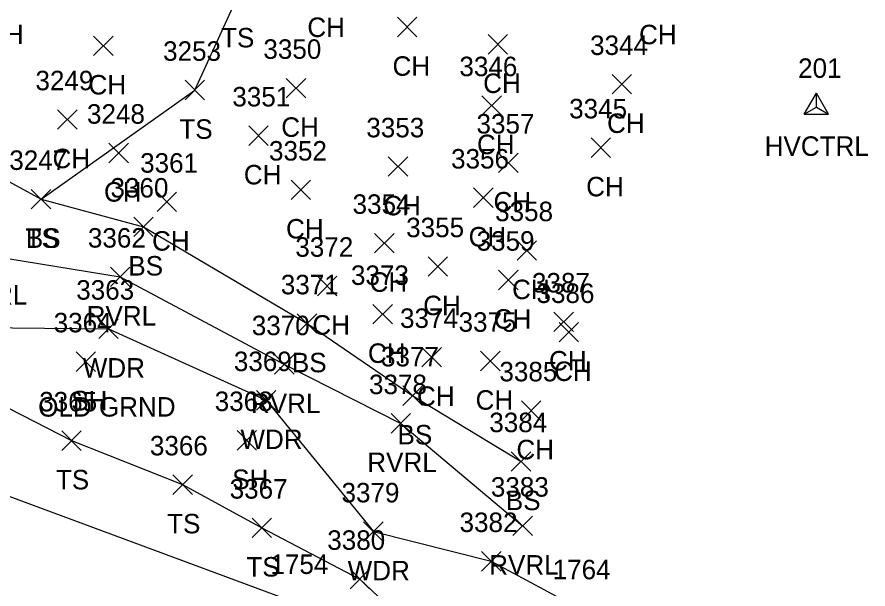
# Model space of a CAD drawing. Extents: x 462930 to 463548, y 29607 to 30453.
# Drawn here: x 463356.77 to 463383.4, y 30103.46 to 30121.35 of the extents above; entities that cross this region are included whole.
import ezdxf

# ---------------------------------------------------------------- set-up
doc = ezdxf.new("R2010")
doc.units = 0
for name, color, linetype in [('C_A', 7, 'Continuous'), ('C_I', 7, 'Continuous'), ('CPSM', 7, 'Continuous'), ('L_A', 7, 'Continuous'), ('L_C', 7, 'Continuous'), ('L_I', 7, 'Continuous'), ('L_TIC', 7, 'Continuous'), ('LAWA', 7, 'Continuous'), ('LAWE', 7, 'Continuous'), ('LELB', 7, 'Continuous')]:
    doc.layers.add(name, color=color, linetype=linetype)

msp = doc.modelspace()

# ---------------------------------------------------------------- linework, layer by layer
at = {"layer": 'CPSM'}
for p, q in [((463381.406, 30118.308), (463381.787, 30118.968)), ((463382.168, 30118.308), (463381.787, 30118.968)), ((463381.787, 30118.528), (463381.787, 30118.968)), ((463381.406, 30118.308), (463381.787, 30118.528)), ((463381.787, 30118.528), (463381.787, 30118.528)), ((463381.787, 30118.528), (463382.168, 30118.308)), ((463381.406, 30118.308), (463382.168, 30118.308))]:
    msp.add_line(p, q, dxfattribs=at)
at = {"layer": 'L_TIC'}
for points in [[(463368.676, 30120.727), (463369.285, 30121.336)], [(463369.285, 30120.727), (463368.676, 30121.336)], [(463359.161, 30120.142), (463359.771, 30120.751)], [(463359.771, 30120.142), (463359.161, 30120.751)], [(463371.514, 30120.189), (463372.124, 30120.799)], [(463372.124, 30120.189), (463371.514, 30120.799)], [(463365.194, 30118.818), (463365.803, 30119.428)], [(463365.803, 30118.818), (463365.194, 30119.428)], [(463375.392, 30118.94), (463376.002, 30119.55)], [(463376.002, 30118.94), (463375.392, 30119.55)], [(463362.028, 30118.757), (463362.637, 30119.366)], [(463362.637, 30118.757), (463362.028, 30119.366)], [(463371.32, 30118.276), (463371.929, 30118.886)], [(463371.929, 30118.276), (463371.32, 30118.886)], [(463358.034, 30117.836), (463358.644, 30118.446)], [(463358.644, 30117.836), (463358.034, 30118.446)], [(463364.022, 30117.33), (463364.631, 30117.94)], [(463364.631, 30117.33), (463364.022, 30117.94)], [(463374.738, 30116.957), (463375.347, 30117.567)], [(463375.347, 30116.957), (463374.738, 30117.567)], [(463359.645, 30116.791), (463360.254, 30117.401)], [(463360.254, 30116.791), (463359.645, 30117.401)], [(463371.839, 30116.483), (463372.449, 30117.093)], [(463372.449, 30116.483), (463371.839, 30117.093)], [(463368.389, 30116.364), (463368.998, 30116.973)], [(463368.998, 30116.364), (463368.389, 30116.973)], [(463365.343, 30115.638), (463365.952, 30116.248)], [(463365.952, 30115.638), (463365.343, 30116.248)], [(463357.213, 30115.345), (463357.823, 30115.955)], [(463357.823, 30115.345), (463357.213, 30115.955)], [(463357.213, 30115.345), (463357.823, 30115.955)], [(463357.823, 30115.345), (463357.213, 30115.955)], [(463371.058, 30115.389), (463371.668, 30115.999)], [(463371.668, 30115.389), (463371.058, 30115.999)], [(463361.15, 30115.259), (463361.76, 30115.869)], [(463361.76, 30115.259), (463361.15, 30115.869)], [(463360.421, 30114.48), (463361.031, 30115.09)], [(463361.031, 30114.48), (463360.421, 30115.09)], [(463367.959, 30113.971), (463368.569, 30114.581)], [(463368.569, 30113.971), (463367.959, 30114.581)], [(463372.42, 30113.742), (463373.03, 30114.351)], [(463373.03, 30113.742), (463372.42, 30114.351)], [(463369.637, 30113.24), (463370.246, 30113.85)], [(463370.246, 30113.24), (463369.637, 30113.85)], [(463359.688, 30112.916), (463360.298, 30113.526)], [(463360.298, 30112.916), (463359.688, 30113.526)], [(463371.843, 30112.819), (463372.453, 30113.428)], [(463372.453, 30112.819), (463371.843, 30113.428)], [(463366.167, 30112.629), (463366.777, 30113.239)], [(463366.777, 30112.629), (463366.167, 30113.239)], [(463367.907, 30111.748), (463368.517, 30112.358)], [(463368.517, 30111.748), (463367.907, 30112.358)], [(463365.54, 30111.455), (463366.15, 30112.064)], [(463366.15, 30111.455), (463365.54, 30112.064)], [(463373.575, 30111.512), (463374.184, 30112.121)], [(463374.184, 30111.512), (463373.575, 30112.121)], [(463359.323, 30111.288), (463359.933, 30111.898)], [(463359.933, 30111.288), (463359.323, 30111.898)], [(463373.734, 30111.183), (463374.344, 30111.793)], [(463374.344, 30111.183), (463373.734, 30111.793)], [(463369.443, 30110.404), (463370.053, 30111.013)], [(463370.053, 30110.404), (463369.443, 30111.013)], [(463371.277, 30110.284), (463371.887, 30110.894)], [(463371.887, 30110.284), (463371.277, 30110.894)], [(463358.617, 30110.265), (463359.227, 30110.875)], [(463359.227, 30110.265), (463358.617, 30110.875)], [(463364.83, 30110.177), (463365.44, 30110.787)], [(463365.44, 30110.177), (463364.83, 30110.787)], [(463364.259, 30109.054), (463364.869, 30109.664)], [(463364.869, 30109.054), (463364.259, 30109.664)], [(463368.847, 30109.199), (463369.456, 30109.809)], [(463369.456, 30109.199), (463368.847, 30109.809)], [(463372.555, 30108.733), (463373.165, 30109.342)], [(463373.165, 30108.733), (463372.555, 30109.342)], [(463368.473, 30108.333), (463369.082, 30108.943)], [(463369.082, 30108.333), (463368.473, 30108.943)], [(463358.164, 30107.793), (463358.774, 30108.403)], [(463358.774, 30107.793), (463358.164, 30108.403)], [(463363.658, 30107.804), (463364.267, 30108.414)], [(463364.267, 30107.804), (463363.658, 30108.414)], [(463372.239, 30107.144), (463372.848, 30107.753)], [(463372.848, 30107.144), (463372.239, 30107.753)], [(463361.646, 30106.417), (463362.256, 30107.027)], [(463362.256, 30106.417), (463361.646, 30107.027)], [(463364.126, 30105.066), (463364.736, 30105.676)], [(463364.736, 30105.066), (463364.126, 30105.676)], [(463372.288, 30105.127), (463372.898, 30105.737)], [(463372.898, 30105.127), (463372.288, 30105.737)], [(463367.615, 30104.948), (463368.225, 30105.557)], [(463368.225, 30104.948), (463367.615, 30105.557)], [(463371.308, 30104.021), (463371.917, 30104.63)], [(463371.917, 30104.021), (463371.308, 30104.63)], [(463367.193, 30103.465), (463367.802, 30104.074)], [(463367.802, 30103.465), (463367.193, 30104.074)]]:
    msp.add_lwpolyline(points, dxfattribs=at)
at = {"layer": 'LAWA'}
for points in [[(463348.213, 30115.888), (463350.137, 30117.27), (463352.155, 30115.4), (463354.611, 30111.648), (463359.628, 30111.593), (463364.564, 30109.359), (463367.92, 30105.253), (463371.613, 30104.325)], [(463376.21, 30084.746), (463374.716, 30092.638), (463372.085, 30098.596), (463365.52, 30103.015), (463354.967, 30106.923), (463349.945, 30110.993), (463346.764, 30113.257)], [(463371.613, 30104.325), (463374.368, 30102.849)]]:
    msp.add_lwpolyline(points, dxfattribs=at)
at = {"layer": 'LAWE'}
msp.add_lwpolyline([(463303.761, 30138.951), (463311.513, 30136.497), (463315.004, 30134.116), (463316.958, 30131.951), (463319.339, 30130.596), (463324.938, 30129.932), (463327.547, 30128.313), (463332.975, 30126.47), (463337.641, 30123.674), (463341.966, 30121.958), (463344.49, 30119.626), (463346.795, 30118.444), (463349.584, 30118.528), (463352.681, 30116.677), (463355.961, 30113.875), (463359.993, 30113.221), (463365.135, 30110.482), (463368.778, 30108.638), (463372.593, 30105.432)], dxfattribs=at)
at = {"layer": 'LELB'}
for points in [[(463303.951, 30140.018), (463311.358, 30137.763), (463317.49, 30134.193), (463325.042, 30130.081), (463328.062, 30128.844), (463333.248, 30127.486), (463337.89, 30124.253), (463342.916, 30122.365), (463345.021, 30120.043), (463346.984, 30119.167), (463349.819, 30119.192), (463353.514, 30117.826), (463357.518, 30115.65), (463360.726, 30114.785), (463365.845, 30111.76), (463369.152, 30109.504), (463372.544, 30107.449)], [(463357.518, 30115.65), (463362.332, 30119.061), (463363.638, 30121.919), (463364.079, 30126.521), (463366.758, 30128.589), (463370.369, 30131.577)], [(463343.625, 30116.989), (463343.551, 30115.889), (463346.121, 30115.132), (463348.213, 30115.888), (463350.835, 30113.965), (463354.177, 30110.301), (463358.469, 30108.098), (463361.951, 30106.722), (463364.431, 30105.371), (463367.498, 30103.77), (463369.557, 30101.829)]]:
    msp.add_lwpolyline(points, dxfattribs=at)

# ---------------------------------------------------------------- texts
at = {"layer": 'C_A'}
msp.add_text('HVCTRL', height=0.6096, dxfattribs=at).set_placement((463380.169, 30117.004))
at = {"layer": 'C_I'}
msp.add_text('201', height=0.6096, dxfattribs=at).set_placement((463381.216, 30119.442))
at = {"layer": 'L_A'}
for s, p in [('CH', (463365.854, 30120.72)), ('CH', (463355.796, 30120.497)), ('TS', (463363.153, 30120.395)), ('CH', (463376.238, 30120.494)), ('CH', (463368.52, 30119.508)), ('CH', (463359.005, 30118.923)), ('CH', (463371.358, 30118.97)), ('TS', (463361.848, 30117.537)), ('CH', (463365.038, 30117.599)), ('CH', (463375.236, 30117.721)), ('CH', (463371.164, 30117.057)), ('CH', (463357.878, 30116.617)), ('CH', (463363.866, 30116.111)), ('CH', (463374.582, 30115.738)), ('CH', (463359.489, 30115.572)), ('CH', (463368.233, 30115.144)), ('CH', (463371.683, 30115.264)), ('CH', (463365.187, 30114.419)), ('TS', (463357.033, 30114.126)), ('BS', (463357.043, 30114.126)), ('CH', (463360.994, 30114.04)), ('CH', (463370.902, 30114.17)), ('BS', (463360.251, 30113.261)), ('CH', (463367.803, 30112.752)), ('CH', (463372.264, 30112.523)), ('RVRL', (463354.915, 30112.351)), ('CH', (463369.481, 30112.021)), ('RVRL', (463358.947, 30111.697)), ('CH', (463371.687, 30111.599)), ('CH', (463366.011, 30111.41)), ('CH', (463367.751, 30110.529)), ('CH', (463373.419, 30110.292)), ('WDR', (463358.824, 30110.069)), ('BS', (463365.37, 30110.236)), ('CH', (463373.578, 30109.964)), ('SH', (463358.461, 30109.046)), ('RVRL', (463364.089, 30108.958)), ('CH', (463369.287, 30109.184)), ('CH', (463371.121, 30109.065)), ('BS', (463368.676, 30107.98)), ('WDR', (463363.76, 30107.835)), ('CH', (463372.399, 30107.514)), ('RVRL', (463367.731, 30107.114)), ('TS', (463357.984, 30106.574)), ('SH', (463363.502, 30106.585)), ('BS', (463372.068, 30105.925)), ('TS', (463361.466, 30105.198)), ('RVRL', (463371.547, 30103.908)), ('TS', (463363.946, 30103.847)), ('WDR', (463367.116, 30103.729))]:
    msp.add_text(s, height=0.6096, dxfattribs=at).set_placement(p)
at = {"layer": 'L_C'}
msp.add_text('OLD GRND', height=0.6096, dxfattribs=at).set_placement((463357.427, 30108.85))
at = {"layer": 'L_I'}
for s, p in [('3344', (463374.704, 30120.159)), ('3253', (463361.339, 30119.976)), ('3350', (463364.478, 30120.038)), ('3346', (463370.614, 30119.496)), ('3249', (463357.343, 30119.055)), ('3351', (463363.506, 30118.549)), ('3248', (463358.956, 30118.01)), ('3345', (463374.049, 30118.176)), ('3353', (463367.7, 30117.583)), ('3357', (463371.15, 30117.702)), ('3352', (463364.654, 30116.857)), ('3247', (463356.524, 30116.564)), ('3247', (463356.524, 30116.564)), ('3361', (463360.62, 30116.478)), ('3356', (463370.353, 30116.608)), ('3360', (463359.692, 30115.7)), ('3354', (463367.27, 30115.19)), ('3358', (463371.732, 30114.961)), ('3355', (463368.948, 30114.46)), ('3362', (463358.985, 30114.135)), ('3359', (463371.152, 30114.038)), ('3372', (463365.478, 30113.849)), ('3373', (463367.219, 30112.968)), ('3371', (463365.024, 30112.674)), ('3387', (463372.886, 30112.731)), ('3363', (463358.62, 30112.507)), ('3386', (463373.028, 30112.403)), ('3374', (463368.755, 30111.623)), ('3364', (463357.914, 30111.485)), ('3370', (463364.115, 30111.396)), ('3375', (463370.588, 30111.503)), ('3369', (463363.554, 30110.273)), ('3377', (463368.158, 30110.419)), ('3385', (463371.866, 30109.952)), ('3378', (463367.784, 30109.552)), ('3365', (463357.461, 30109.012)), ('3368', (463362.955, 30109.024)), ('3384', (463371.55, 30108.363)), ('3366', (463360.926, 30107.636)), ('3367', (463363.423, 30106.285)), ('3383', (463371.599, 30106.347)), ('3379', (463366.924, 30106.167)), ('3382', (463370.619, 30105.24)), ('3380', (463366.478, 30104.684)), ('1754', (463364.699, 30103.929)), ('1764', (463373.533, 30103.763))]:
    msp.add_text(s, height=0.6096, dxfattribs=at).set_placement(p)

doc.saveas('drawing.dxf')
